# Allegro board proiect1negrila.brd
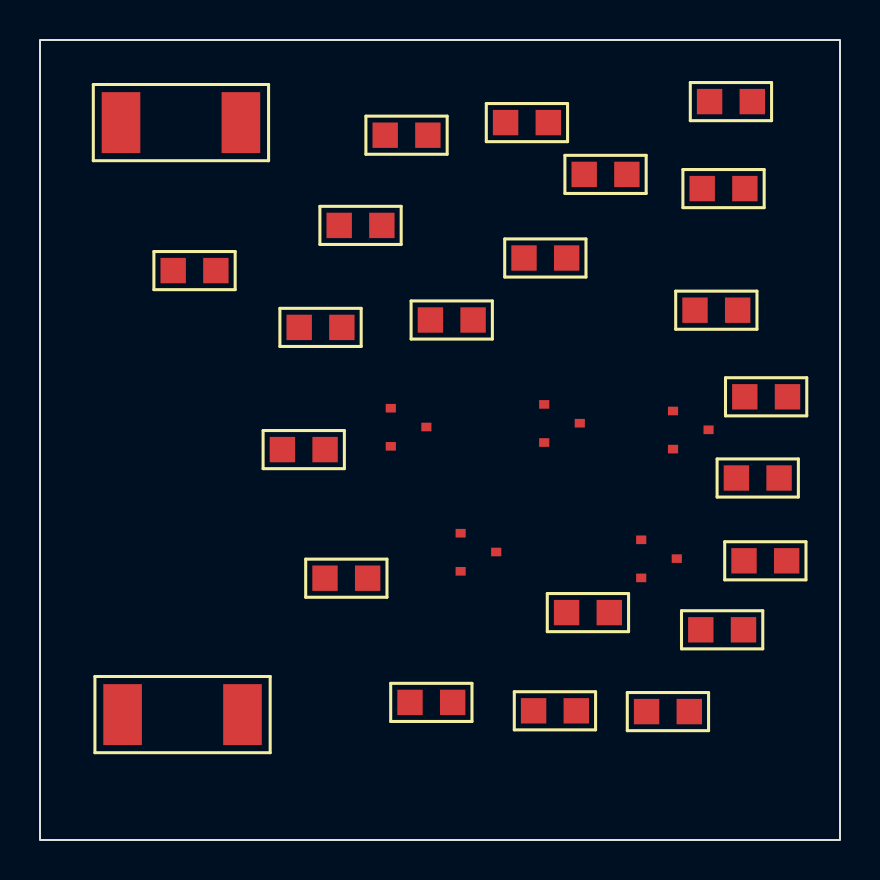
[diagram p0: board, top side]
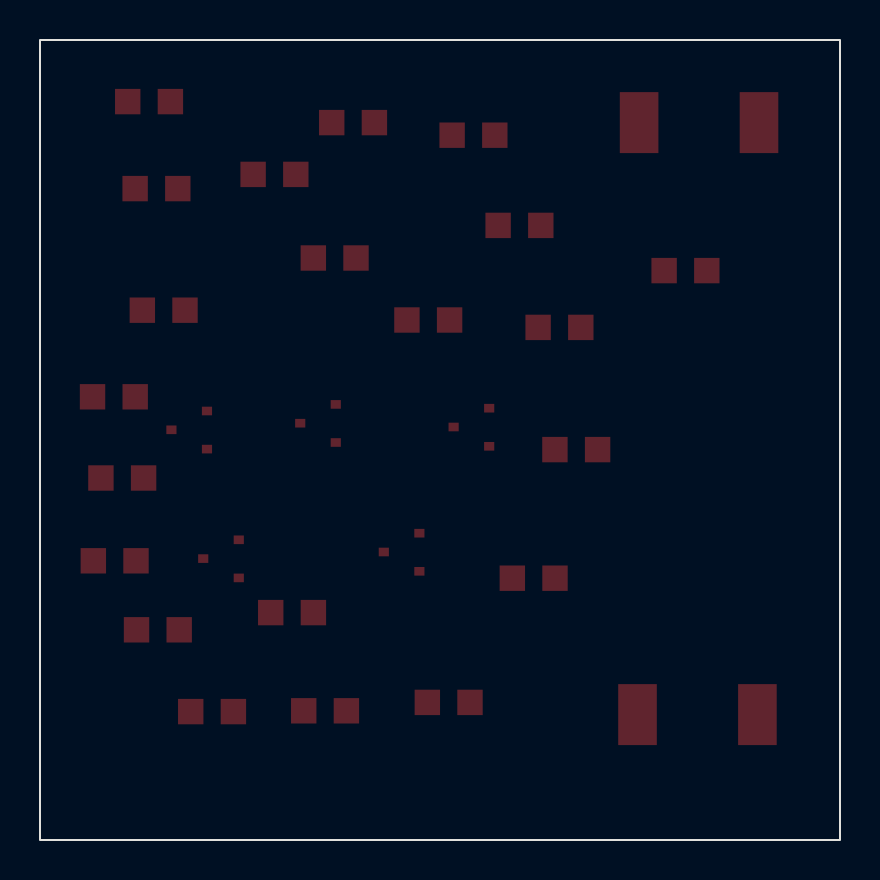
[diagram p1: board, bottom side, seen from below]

Outline 40 x 40 mm; copper layers: TOP, BOTTOM. Coordinates in mm from the lower left corner of the outline.
Outline path: rectangle 0,0 40,40

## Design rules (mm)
constraint set DEFAULT: min track width 0.127

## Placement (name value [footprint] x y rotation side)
C1  1n  [SMC0805]  23.28 35.87 0 top
C2  1n  [SMC0805]  24.2 29.1 0 top
J1  CON2  [SMR2512]  4.05 35.87 0 top
J2  CON2  [SMR2512]  4.13 6.27 0 top
Q1  BC856B  [SOT23]  18.43 20.65 0 top
Q2  BC856B  [SOT23]  26.1 20.84 0 top
Q3  BC856B  [SOT23]  32.54 20.51 0 top
Q4  BC856B  [SOT23]  21.92 14.4 0 top
Q5  BC846B  [SOT23]  30.95 14.07 0 top
R1  15k  [SMR0805]  18.5 6.88 0 top
R2  820  [SMR0805]  24.68 6.46 0 top
R3  15k  [SMR0805]  30.33 6.42 0 top
R4  820  [SMR0805]  33.04 10.51 0 top
R5  100k  [SMR0805]  32.75 26.49 0 top
R6  33  [SMR0805]  33.48 36.92 0 top
R8  100  [SMR0805]  33.11 32.57 0 top
R9  150  [SMR0805]  35.24 22.16 0 top
R10  150  [SMR0805]  34.82 18.1 0 top
R11  10  [SMR0805]  35.2 13.96 0 top
R12  150  [SMR0805]  26.33 11.37 0 top
R13  33  [SMR0805]  14.25 13.09 0 top
R14  150  [SMR0805]  12.12 19.52 0 top
R15  150  [SMR0805]  12.96 25.63 0 top
R16  150  [SMR0805]  14.96 30.73 0 top
R17  10k  [SMR0805]  17.26 35.24 0 top
R18  470  [SMR0805]  19.52 26 0 top
R19  15k  [SMR0805]  27.21 33.28 0 top
R20  510  [SMR0805]  6.66 28.47 0 top

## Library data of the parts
C1 C2 = C
J1 J2 = CON2
Q1-Q4 = BC856B
Q5 = BC846B
R1-R6 R8-R20 = R

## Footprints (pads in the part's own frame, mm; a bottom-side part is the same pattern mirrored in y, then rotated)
SMC0805
  rect 1.27x1.27 smd: 1(0,0) 2(2.134,0)
SMR0805
  rect 1.27x1.27 smd: 1(0,0) 2(2.134,0)
SMR2512
  rect 1.93x3.048 smd: 1(0,0) 2(5.994,0)
SOT23
  rect 0.508x0.432 smd: 1(-0.889,0.94) 2(-0.889,-0.965) 3(0.889,0)

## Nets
GND: C1.1 J1.2 J2.1 R1.1 R6.1
VIN: Q1.1 R5.2 R17.1 R19.2
VOUT: C2.2 Q4.3 Q5.3 R17.2 R18.2
N07023: C1.2 Q2.1 R2.2 R3.1
N07031: R3.2 R4.1
N07035: C2.1 R4.2
N07047: J1.1 Q3.2(E) R9.2 R16.2
N07123: R9.1 R14.2
N07171: R15.2 R16.1
N07211: R8.2 R14.1
N07215: R1.2 R2.1
N07279: Q3.1 Q3.3 Q4.1 Q4.2(E) R12.2 R15.1
N07291: Q1.2(E) Q2.2(E) R8.1
N07445: Q2.3 Q5.1 R10.2
N07449: J2.2 Q1.3 Q5.2(E) R11.1 R13.1
N07749: R5.1
N073371: R6.2 R18.1
N075191: R12.1 R13.2
N075691: R10.1 R11.2
N077411: R19.1 R20.2
N077611: R20.1
